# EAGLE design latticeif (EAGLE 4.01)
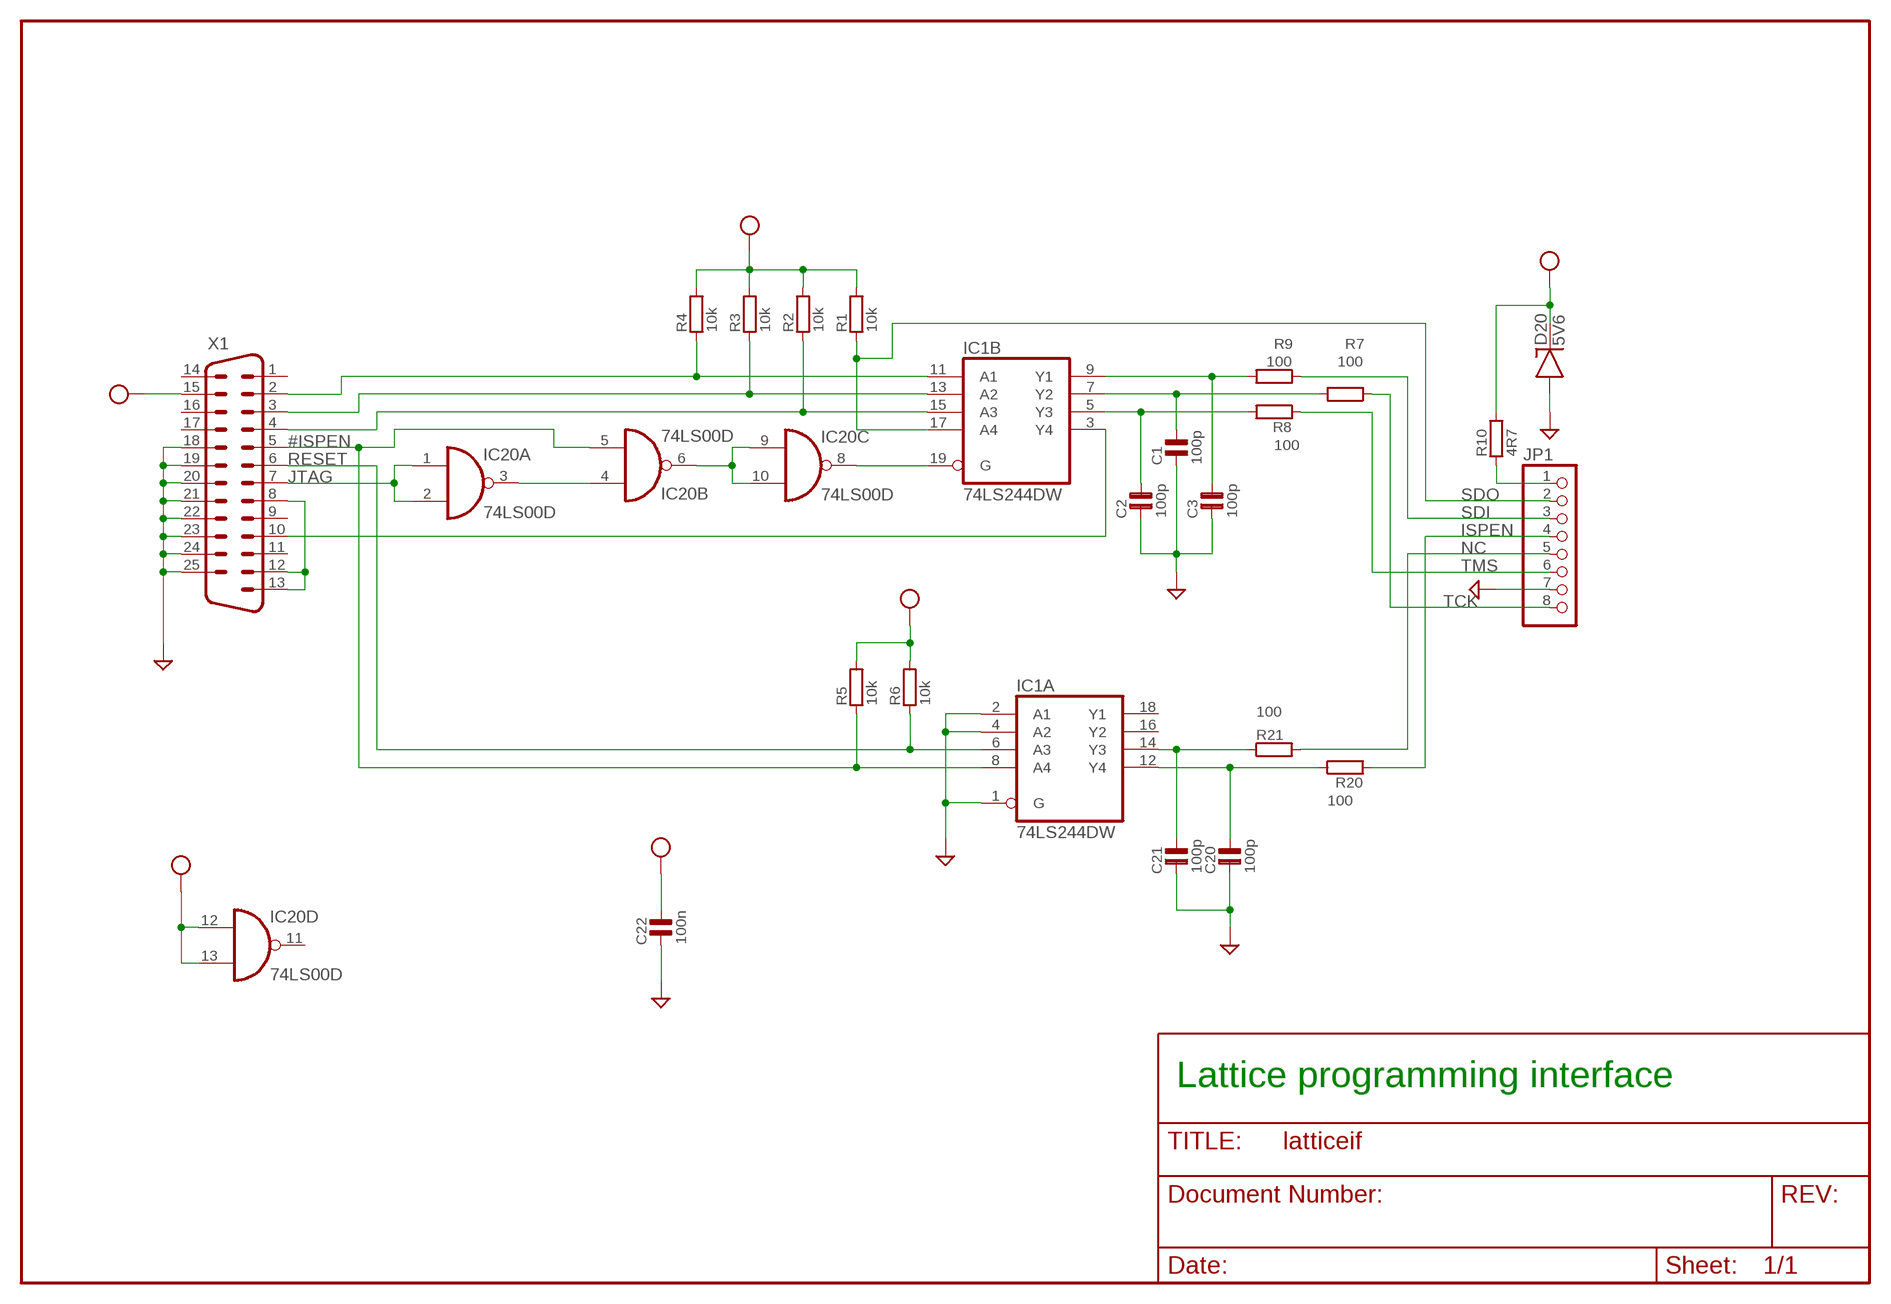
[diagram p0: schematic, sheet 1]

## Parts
C1  100p  C0805  [0805]
C2  100p  C0805  [0805]
C3  100p  C0805  [0805]
C20  100p  C0805  [0805]
C21  100p  C0805  [0805]
C22  100n  C1206  [1206]
D20  5V6  BZV55  [SOD80]
IC1  74LS244DW  [SO20W]
IC20  74LS00D  [SO14]
JP1  PINHD-1X8  [1X08]
R1  10k  R1206  [1206]
R2  10k  R1206  [1206]
R3  10k  R1206  [1206]
R4  10k  R1206  [1206]
R5  10k  R1206  [1206]
R6  10k  R1206  [1206]
R7  100  R1206  [1206]
R8  100  R1206  [1206]
R9  100  R1206  [1206]
R10  4R7  R1206  [1206]
R20  100  R1206  [1206]
R21  100  R1206  [1206]
X1  M25D  [M25D]

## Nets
#ISPEN: IC1.8(A:A4) IC20.5(B:I1) R5.1 X1.5
GND: C1.1 C2.1 C3.1 C20.1 C21.1 C22.1 D20.1(A) IC1.1(A:G) IC1.2(A:A1) IC1.4(A:A2) JP1.7 X1.18 X1.19 X1.20 X1.21 X1.22 X1.23 X1.24 X1.25
ISPEN: JP1.4 R20.2
JTAG: IC20.1(A:I0) IC20.2(A:I1) X1.7
N$1: IC20.3(A:O) IC20.4(B:I0)
N$2: IC20.6(B:O) IC20.9(C:I0) IC20.10(C:I1)
N$3: JP1.1 R10.1
N$4: IC1.19(B:G) IC20.8(C:O)
N$5: IC1.11(B:A1) R4.1 X1.2
N$6: C3.2 IC1.9(B:Y1) R9.2
N$7: C1.2 IC1.7(B:Y2) R7.2
N$8: C2.2 IC1.5(B:Y3) R8.2
N$10: IC1.13(B:A2) R3.1 X1.3
N$11: IC1.15(B:A3) R2.1 X1.4
N$12: X1.8 X1.12 X1.13
N$15: IC1.3(B:Y4) X1.10
N$19: C21.2 IC1.14(A:Y3) R21.1
N$20: C20.2 IC1.12(A:Y4) R20.1
NC: JP1.5 R21.2
RESET: IC1.6(A:A3) R6.1 X1.6
SDI: JP1.3 R9.1
SDO: IC1.17(B:A4) JP1.2 R1.1
TCK: JP1.8 R7.1
TMS: JP1.6 R8.1
VCC: C22.2 D20.2(K) IC20.12(D:I0) IC20.13(D:I1) R1.2 R2.2 R3.2 R4.2 R5.2 R6.2 R10.2 X1.15
Unconnected: IC1.16(A:Y2) IC1.18(A:Y1) IC20.11(D:O) X1.1 X1.9 X1.11 X1.14 X1.16 X1.17

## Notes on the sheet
- Lattice programming interface

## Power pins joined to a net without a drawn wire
GND: IC1.10(P:GND) IC20.7(P:GND)
VCC: IC1.20(P:VCC) IC20.14(P:VCC)

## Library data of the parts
C1-C3 C20 C21 = weini:C0805
C22 = weini:C1206
D20 = weini:BZV55
IC1 = 74xx-eu:74*244: Octal BUFFER and LINE DRIVER, 3-state
IC20 = 74xx-eu:74*00: Quad 2-input NAND gate
JP1 = pinhead:PINHD-1X8: PIN HEADER
R1-R10 R20 R21 = weini:R1206
X1 = con-subd:M25D: HARTING SUB-D

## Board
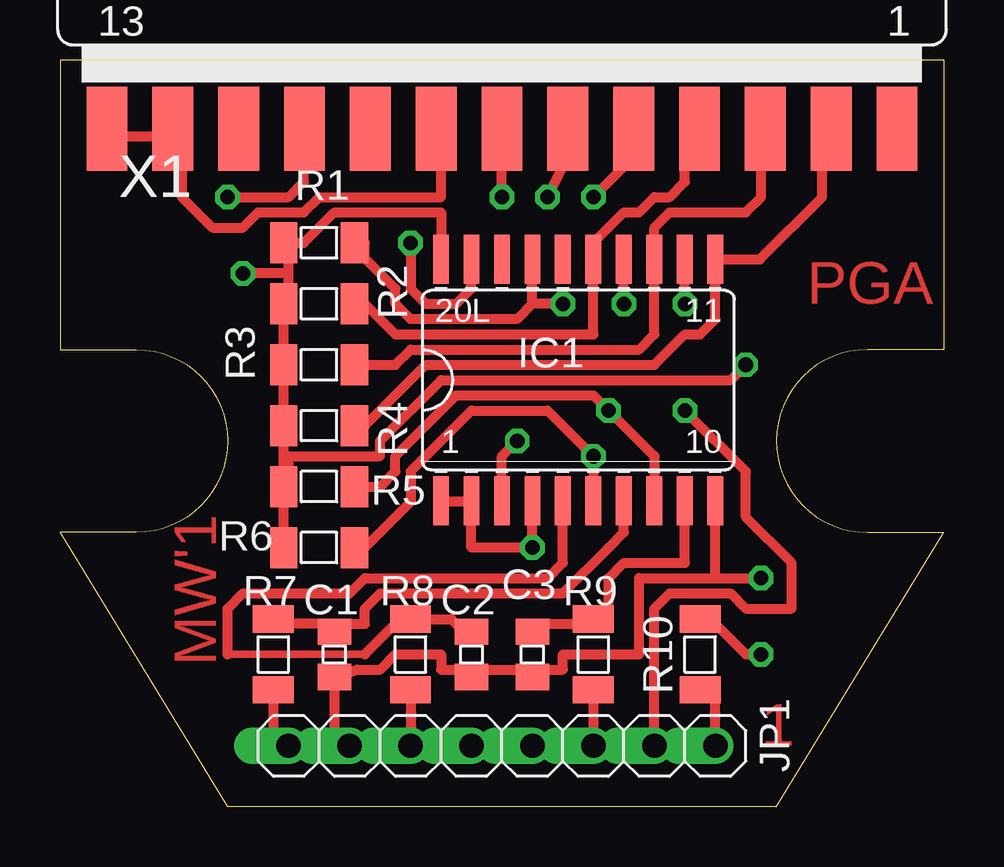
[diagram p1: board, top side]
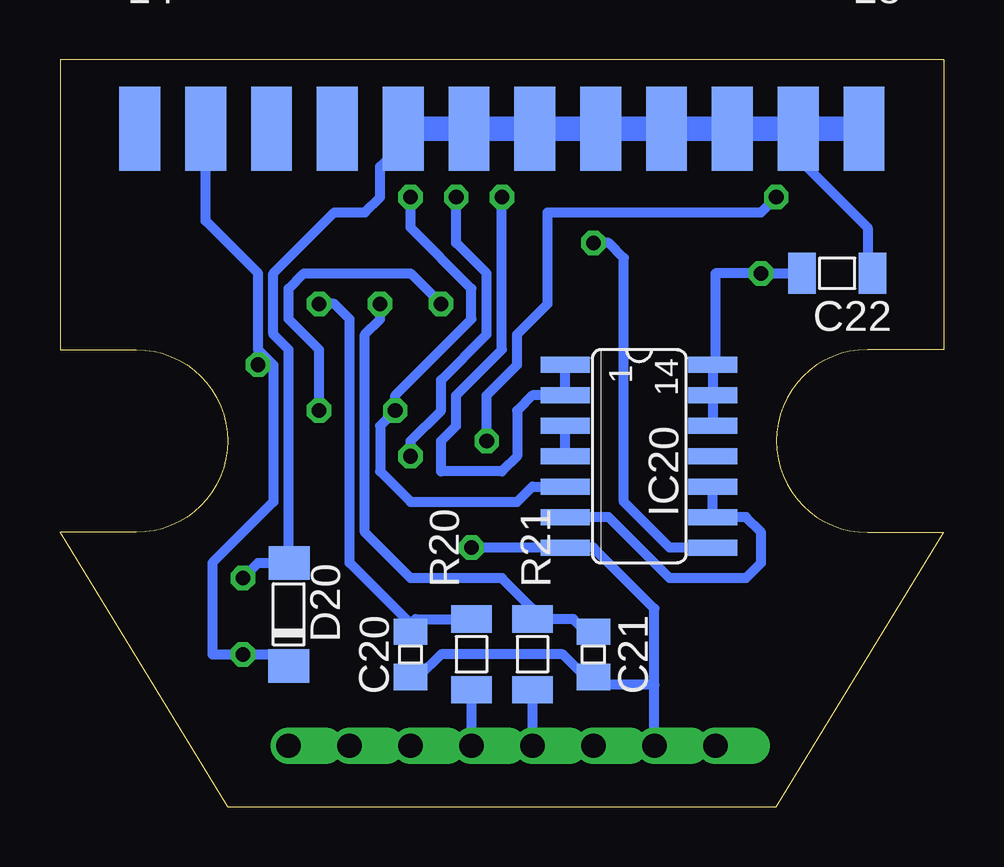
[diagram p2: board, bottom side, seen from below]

Size 36.83 x 31.11 mm. Coordinates in mm from the lower left corner, seen from the top.
Outline: 0,31.11 36.83,31.11 36.83,19.05 33.66,19.05 arc180 33.66,11.43 36.83,11.43 29.84,0 6.98,0 0,11.43 3.17,11.43 arc180 3.17,19.05 0,19.05 0,31.11
Copper layers used: Top, Bottom

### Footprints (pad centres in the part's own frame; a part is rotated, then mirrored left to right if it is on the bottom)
0805 = smd 1.092 x 1.397: 1 -0.94,0; 2 0.94,0
1206 = smd 1.143 x 1.702: 1 -1.473,0; 2 1.473,0
SOD80 = smd 1.397 x 1.702: 1 1.905,-0.025; 2 -2.388,0
SO20W = smd 0.66 x 2.032: 1 -5.715,-5.029; 2 -4.445,-5.029; 3 -3.175,-5.029; 4 -1.905,-5.029; 5 -0.635,-5.029; 6 0.635,-5.029; 7 1.905,-5.029; 8 3.175,-5.029; 9 4.445,-5.029; 10 5.715,-5.029; 11 5.715,5.029; 12 4.445,5.029; 13 3.175,5.029; 14 1.905,5.029; 15 0.635,5.029; 16 -0.635,5.029; 17 -1.905,5.029; 18 -3.175,5.029; 19 -4.445,5.029; 20 -5.715,5.029
SO14 = smd 0.66 x 2.032: 1 -3.81,-3.073; 2 -2.54,-3.073; 3 -1.27,-3.073; 4 0,-3.073; 5 1.27,-3.073; 6 2.54,-3.073; 7 3.81,-3.073; 8 3.81,3.073; 9 2.54,3.073; 10 1.27,3.073; 11 0,3.073; 12 -1.27,3.073; 13 -2.54,3.073; 14 -3.81,3.073
1X08 = drill 1.016 offset: 1 -8.89,0; 2 -6.35,0; 3 -3.81,0; 4 -1.27,0; 5 1.27,0; 6 3.81,0; 7 6.35,0; 8 8.89,0
M25D = smd 1.7 x 3.5: 1 16.459,-6.045; 2 13.716,-6.045; 3 10.973,-6.045; 4 8.23,-6.045; 5 5.486,-6.045; 6 2.743,-6.045; 7 0,-6.045; 8 -2.743,-6.045; 9 -5.486,-6.045; 10 -8.23,-6.045; 11 -10.973,-6.045; 12 -13.716,-6.045; 13 -16.459,-6.045 | smd 1.7 x 3.5 bottom: 14 15.088,-6.045; 15 12.344,-6.045; 16 9.601,-6.045; 17 6.858,-6.045; 18 4.115,-6.045; 19 1.372,-6.045; 20 -1.372,-6.045; 21 -4.115,-6.045; 22 -6.858,-6.045; 23 -9.601,-6.045; 24 -12.344,-6.045; 25 -15.088,-6.045

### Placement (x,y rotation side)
C1  11.43,6.35 90 top
C2  17.14,6.35 90 top
C3  19.68,6.35 90 top
C20  22.22,6.35 90 bottom
C21  14.6,6.35 90 bottom
C22  4.44,22.23 180 bottom
D20  27.3,8.26 90 bottom
IC1  21.59,17.78 0 top
IC20  12.7,14.61 270 bottom
JP1  18.41,2.54 180 top
R1  10.79,23.5 180 top
R2  10.79,20.95 180 top
R3  10.79,18.41 180 top
R4  10.79,15.88 180 top
R5  10.79,13.34 180 top
R6  10.79,10.79 180 top
R7  8.89,6.35 90 top
R8  14.6,6.35 90 top
R9  22.22,6.35 90 top
R10  26.67,6.35 90 top
R20  19.68,6.35 270 bottom
R21  17.14,6.35 270 bottom
X1  18.41,34.29 0 top

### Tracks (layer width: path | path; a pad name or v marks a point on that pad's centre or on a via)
#ISPEN  (via drill 0.61)
  Top 0.406: IC1.8 24.77,14.61 v22.86,16.51 22.22,17.14 16.51,17.14 13.97,14.61 13.97,13.97 13.33,13.34 R5.1 | X1.5 23.9,27.08 v22.22,25.4
  Bottom 0.406: v22.22,25.4 22.22,24.13 19.68,21.59 19.68,20.32 22.86,17.14 v22.86,16.51 23.49,15.88 23.49,13.97 22.22,12.7 17.78,12.7 17.14,13.34 IC20.5
GND  (via drill 0.61)
  Top 0.406: JP1.7 11.43,3.17 C1.1 12.37,5.71 13.33,5.71 13.97,6.35 15.88,6.35 15.88,5.71 17.14,5.71 | 17.14,5.71 C2.1 | 19.68,5.71 C3.1 | 17.14,5.71 19.68,5.71 | 19.68,5.71 20.95,5.71 20.95,6.35 24.13,6.35 24.13,9.53 27.3,9.53 | IC1.1 15.93,12.7 17.14,12.7 IC1.2 17.14,10.79 v19.68,10.79 IC1.4 | 27.3,9.53 v29.21,9.53 | 27.3,9.53 IC1.10
  Bottom 0.406: C20.1 21.89,5.41 20.95,6.35 15.88,6.35 14.6,5.08 | 14.6,5.08 C21.1 | v19.68,10.79 IC20.7 14.6,10.79 12.06,8.26 12.06,5.08 | JP1.7 12.06,5.08 | 12.06,5.08 14.6,5.08 | v29.21,9.53 28.57,10.16 27.3,10.16 | 27.3,10.16 D20.1 | 27.3,10.16 27.3,19.05 27.94,19.68 27.94,22.23 25.4,24.77 24.13,24.77 23.49,25.4 23.49,26.67 22.53,27.64 X1.18 | 6.35,27.94 5.71,27.3 5.71,26.67 3.17,24.13 3.17,22.86 | 6.35,27.94 6.07,28.22 X1.24 | 6.65,28.25 6.35,27.94 | 6.35,27.94 6.04,28.25 | 5.38,28.25 5.41,28.25 5.71,27.94 6.35,27.94 | C22.1 3.17,22.43 3.17,22.86 | 3.17,22.86 3.17,22.23
  Bottom 1.016: 6.04,28.25 X1.24 | X1.25 5.38,28.25 5.71,28.57 | 14.3,28.27 14.6,28.57 | 14.3,28.27 X1.21 16.81,28.25 17.04,28.47 | 14.3,28.27 14.27,28.25 X1.22 11.56,28.07 11.43,27.94 11.12,28.25 X1.23 6.65,28.25 | 17.04,28.47 17.14,28.57 | 17.04,28.47 X1.20 19.36,28.25 19.68,28.57 19.79,28.47 X1.19 21.89,28.25 22.22,28.57 22.53,28.27 X1.18
ISPEN
  Bottom 0.406: 19.68,5.08 R20.2 JP1.4
JTAG  (via drill 0.61)
  Top 0.406: v18.41,25.4 X1.7
  Bottom 0.406: v18.41,25.4 18.41,19.05 20.32,17.14 20.32,15.88 20.95,15.24 20.95,13.97 18.41,13.97 17.78,14.61 17.78,16.51 17.14,17.14 15.88,17.14 | IC20.1 15.77,17.25 15.88,17.14 | IC20.2 15.88,17.14
N$1
  Bottom 0.406: IC20.4 15.88,14.61 15.77,14.71 IC20.3
N$2
  Bottom 0.406: IC20.10 9.63,12.17 9.52,12.06 IC20.9 8.25,12.06 7.62,11.43 7.62,10.16 8.25,9.53 11.43,9.53 13.97,12.06 IC20.6 15.88,12.06
N$3
  Top 0.406: R10.1 26.87,4.88 27.3,4.45 JP1.1
N$4  (via drill 0.61)
  Top 0.406: IC1.19 17.14,21.59 16.51,20.95 15.24,20.95 14.6,21.59 v14.6,23.5
  Bottom 0.406: v14.6,23.5 13.97,23.5 13.33,22.86 13.33,12.7 11.43,10.79 IC20.8 10.16,10.79
N$5
  Top 0.406: R4.1 12.7,15.88 15.24,18.41 24.77,18.41 26.04,19.68 26.67,19.68 27.3,20.32 IC1.11 29.16,22.81 31.75,25.4 31.75,27.3 32.38,27.94 32.13,28.19 X1.2
N$6
  Top 0.406: C3.2 20.02,7.62 22.22,7.62 R9.2 22.86,8.46 22.86,9.53 23.49,10.16 26.04,10.16 IC1.9
N$7
  Top 0.406: C1.2 11.43,7.62 | R7.2 9.09,7.62 11.43,7.62 | 11.43,7.62 12.7,7.62 12.7,8.26 13.33,8.89 20.95,8.89 22.86,10.79 23.49,11.43 IC1.7
N$8
  Top 0.305: 12.7,6.35 6.98,6.35
  Top 0.406: 12.7,6.35 13.97,7.62 14.4,7.62 R8.2 16.31,7.82 17.14,6.99 C2.2 | 6.98,6.35 6.98,8.26 7.62,8.89 12.06,8.89 12.7,9.53 20.32,9.53 20.95,10.16 IC1.5
N$10
  Top 0.406: R3.1 13.97,18.41 14.6,19.05 24.13,19.05 24.77,19.68 IC1.13 24.77,24.13 25.4,24.77 28.57,24.77 29.21,25.4 29.21,27.94 29.39,28.12 X1.3
N$11
  Top 0.406: R2.1 12.7,20.95 13.97,19.68 22.22,19.68 IC1.15 22.22,23.5 23.49,24.77 24.13,24.77 24.77,25.4 25.4,25.4 26.04,26.04 26.04,27.3 26.67,27.94 26.64,27.96 X1.4
N$12
  Top 0.406: X1.13 2.26,27.94 4.44,27.94 4.44,27.99 X1.12 5.08,27.86 5.08,25.4 6.35,24.13 7.62,24.13 8.25,24.77 10.16,24.77 10.79,25.4 15.88,25.4 15.88,28.04 X1.8
N$15  (via drill 0.61)
  Top 0.406: IC1.3 18.41,14.61 v19.05,15.24 | X1.10 10.18,27.96 10.16,27.3 10.16,26.04 9.52,25.4 v6.98,25.4
  Bottom 0.406: v6.98,25.4 7.62,24.77 16.51,24.77 16.51,20.95 17.78,19.68 17.78,18.41 19.05,17.14 v19.05,15.24
N$19  (via drill 0.61)
  Top 0.406: v23.49,20.95 IC1.14
  Bottom 0.406: v23.49,20.95 23.49,20.32 24.13,19.68 24.13,11.43 22.22,9.53 18.41,9.53 17.14,8.26 R21.1 15.44,7.82 14.6,6.99 C21.2
N$20  (via drill 0.61)
  Top 0.406: v26.04,20.95 IC1.12
  Bottom 0.406: v26.04,20.95 25.4,20.95 24.77,20.32 24.77,10.16 22.22,7.62 | R20.1 22.02,7.82 22.22,7.62 | C20.2 22.22,7.62
NC
  Bottom 0.406: 17.14,5.08 R21.2 JP1.5
RESET  (via drill 0.61)
  Top 0.406: IC1.6 v22.22,14.61 20.32,16.51 17.14,16.51 14.6,13.97 14.6,12.7 12.7,10.79 R6.1 | X1.6 21.16,27.51 20.95,27.3 20.95,26.67 v20.32,25.4
  Bottom 0.406: v20.32,25.4 20.32,23.5 19.05,22.23 19.05,19.68 20.95,17.78 20.95,16.51 22.22,15.24 v22.22,14.61
SDI
  Top 0.406: R9.1 JP1.3
SDO  (via drill 0.61)
  Top 0.406: 19.68,20.95 IC1.17 | 19.68,20.95 19.05,20.32 14.6,20.32 13.97,20.95 13.97,21.59 12.7,22.86 12.7,23.5 R1.1 | JP1.2 24.77,8.26 25.4,8.89 27.94,8.89 28.57,8.26 30.48,8.26 30.48,10.16 28.57,12.06 28.57,13.97 v26.04,16.51 | v20.95,20.95 19.68,20.95
  Bottom 0.406: v20.95,20.95 22.22,22.23 26.67,22.23 27.3,21.59 27.3,20.32 26.04,19.05 v26.04,16.51
TCK
  Top 0.406: R7.1 8.89,3.17 JP1.8
TMS
  Top 0.406: R8.1 JP1.6
VCC  (via drill 0.61)
  Top 0.406: R10.2 26.67,7.62 27.3,7.62 28.57,6.35 v29.21,6.35 | 9.52,20.95 R2.2 9.32,18.62 9.52,18.41 | 9.52,20.95 9.52,22.23 | 9.52,18.41 R3.2 | 9.52,18.41 9.32,18.21 R4.2 9.32,13.54 | 9.32,13.54 9.52,13.34 R5.2 9.32,11 9.52,10.79 R6.2 | IC1.20 15.88,24.77 11.43,24.77 10.16,23.5 9.52,23.5 | 9.52,20.95 9.52,20.32 | 9.52,23.5 R1.2 | 9.52,22.23 v7.62,22.23 | 9.52,22.23 9.52,23.5 | v28.57,18.41 27.94,17.78 15.88,17.78 13.33,15.24 13.33,14.61 9.52,14.61 9.52,13.74 9.32,13.54
  Bottom 0.406: 9.52,17.14 IC20.13 | IC20.14 9.63,17.25 9.52,17.14 | IC20.12 9.63,17.04 9.52,17.14 | D20.2 27.94,6.35 v29.21,6.35 30.48,6.35 30.48,10.16 27.94,12.7 27.94,18.41 | X1.15 30.76,24.41 28.57,22.23 28.57,19.05 27.94,18.41 | IC20.14 10.16,18.41 | IC20.14 9.52,18.41 9.52,22.23 v7.62,22.23 C22.2 | v28.57,18.41 27.94,18.41

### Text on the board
Top: PGA | MW'1 | 1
